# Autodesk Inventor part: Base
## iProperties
Shininess: 77.0
Length Units: 11269
Angle Units: 11279
Time Units: 11290
Mass Units: 11283
Length Display Precision: 3
Angle Display Precision: 2
Created: 2002-02
Part Number: Base
Document SubType Name: Modeling
Designer: ***
Density: 0.0
Volumn: 0.0
Area: 0.0
PropertySet Name: Model Information
Control State: 0
Master: False
Checked Out: False
Author: ***
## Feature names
1. Extrusion1
2. Extrusion3
3. Extrusion4
4. Hole1
5. Rectangular Pattern1
6. Hole2
7. Rectangular Pattern2
